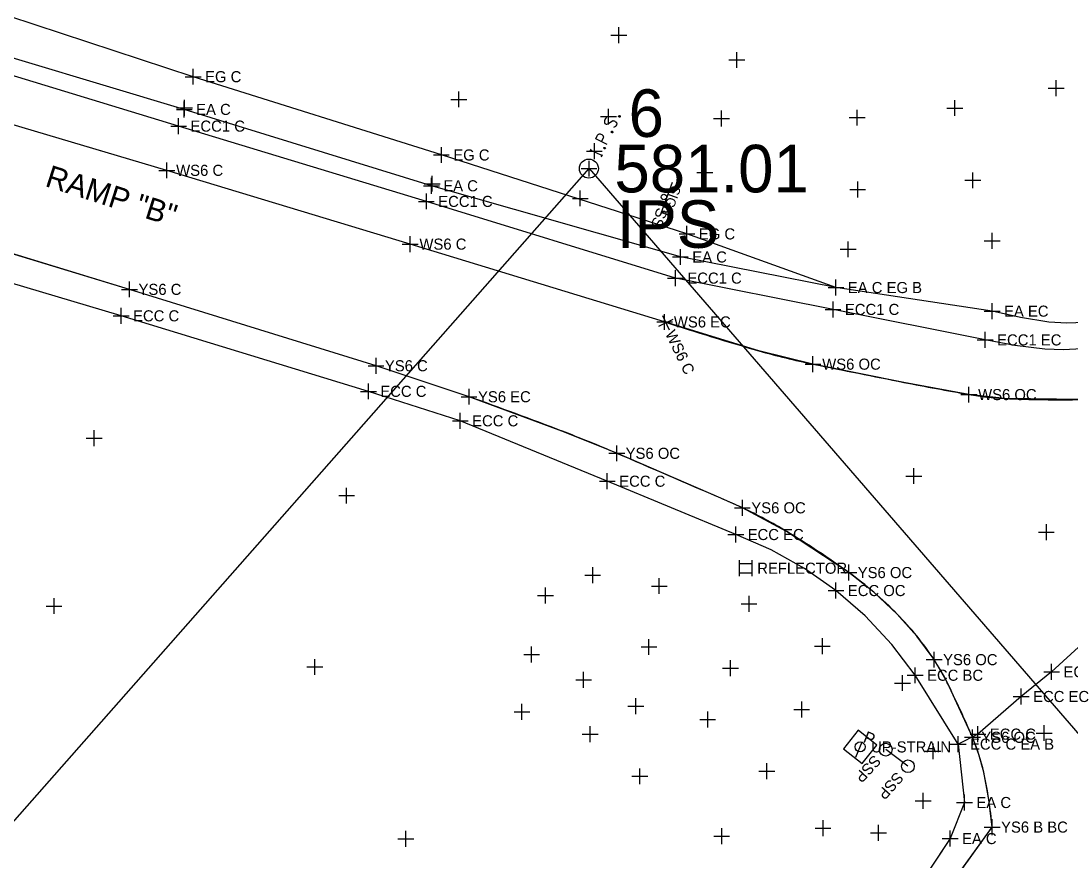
# Model space of a CAD drawing. Extents: x 1324236 to 1326110, y 459090 to 460782.
# Drawn here: x 1325183.3 to 1325315.8, y 460303.9 to 460409.8 of the extents above; entities that cross this region are included whole.
import ezdxf

# ---------------------------------------------------------------- set-up
doc = ezdxf.new("R2010")
doc.units = 0
for name, color, linetype in [('DR_X_Ditch', 7, 'Continuous'), ('DT_X_Contour_Major', 7, 'Continuous'), ('DT_X_Contour_Minor', 7, 'Continuous'), ('DT_X_Terrain_Ground_Line', 7, 'Continuous'), ('DT_X_Void', 7, 'Continuous'), ('DV_X_Property_Line', 7, 'Continuous'), ('E-RW-ODOT', 7, 'Continuous'), ('PM_X_Edge_Line', 7, 'Continuous'), ('PV_X_Shoulder', 7, 'Continuous'), ('PV_X_Shoulder_Aggregate', 7, 'Continuous'), ('RD_X_Concrete_Barrier', 7, 'Continuous'), ('RD_X_Text', 7, 'Continuous'), ('RW_X_CL', 7, 'Continuous'), ('RW_X_Esmt_SH', 7, 'Continuous'), ('SG_X_Foundation', 7, 'Continuous')]:
    doc.layers.add(name, color=color, linetype=linetype)

msp = doc.modelspace()

# ---------------------------------------------------------------- linework, layer by layer
at = {"layer": 'DR_X_Ditch'}
for p, q in [((1325301.57, 460318.51), (1325302.38, 460311.14)), ((1325302.38, 460311.14), (1325300.56, 460306.59)), ((1325300.56, 460306.59), (1325287.22, 460286.49))]:
    msp.add_line(p, q, dxfattribs=at)
for points in [[(1325317.23, 460361.99), (1325307.45, 460362.12), (1325307.45, 460362.12), (1325302.92, 460362.62), (1325302.92, 460362.62), (1325294.72, 460364.16), (1325294.72, 460364.16), (1325283.25, 460366.46), (1325283.25, 460366.46), (1325276.4, 460368.15), (1325276.4, 460368.15), (1325264.53, 460371.79), (1325264.53, 460371.79), (1325232.42, 460381.61), (1325201.72, 460390.92), (1325171.39, 460399.9)], [(1325305.86, 460308.04), (1325305.44, 460311.51), (1325304.8, 460314.95), (1325304.8, 460314.95), (1325304.19, 460317.19), (1325303.38, 460319.37), (1325303.38, 460319.37), (1325300.17, 460326.34), (1325300.17, 460326.34), (1325298.54, 460329.17), (1325298.54, 460329.17), (1325296.34, 460332.15), (1325293.87, 460334.92), (1325293.87, 460334.92), (1325290.94, 460337.67), (1325287.78, 460340.16), (1325287.78, 460340.16), (1325279.93, 460345.35), (1325279.93, 460345.35), (1325274.34, 460348.33), (1325274.34, 460348.33), (1325271.63, 460349.54), (1325271.63, 460349.54), (1325258.49, 460355.21), (1325258.49, 460355.21), (1325251.56, 460358.02), (1325251.56, 460358.02), (1325239.85, 460362.35), (1325239.85, 460362.35), (1325228.11, 460366.26), (1325197.01, 460375.9), (1325166.97, 460385.03)], [(1325301.57, 460318.51), (1325302.38, 460311.14), (1325300.56, 460306.59), (1325287.22, 460286.49), (1325268.79, 460261.45), (1325251.49, 460239.07), (1325233.13, 460213.12), (1325215.71, 460188.93), (1325205.67, 460177.31)], [(1325301.15, 460301.5), (1325305.86, 460308.04)]]:
    msp.add_lwpolyline(points, dxfattribs=at)
at = {"layer": 'DT_X_Contour_Major'}
for points in [[(1325257.22, 460397.56), (1325257.19, 460397.55), (1325257.15, 460397.53), (1325257.08, 460397.45), (1325257, 460397.35), (1325256.97, 460397.27), (1325256.95, 460397.24), (1325256.93, 460397.1), (1325256.94, 460396.96), (1325257, 460396.84), (1325257.08, 460396.78), (1325257.15, 460396.75), (1325257.25, 460396.73), (1325257.37, 460396.77), (1325257.97, 460397.16), (1325258.04, 460397.19), (1325258.09, 460397.18), (1325258.17, 460397.17), (1325258.24, 460397.14), (1325258.3, 460397.1), (1325258.34, 460397.07), (1325258.39, 460397.02), (1325258.43, 460396.98), (1325258.45, 460396.94), (1325258.47, 460396.9), (1325258.48, 460396.85), (1325258.49, 460396.8), (1325258.48, 460396.77), (1325258.45, 460396.67), (1325258.39, 460396.53), (1325258.32, 460396.46), (1325258.18, 460396.36), (1325258.07, 460396.32)], [(1325258.72, 460397.75), (1325258.75, 460397.8), (1325258.78, 460397.82), (1325258.84, 460397.83), (1325258.9, 460397.8), (1325258.93, 460397.75), (1325258.94, 460397.71), (1325258.92, 460397.66), (1325258.88, 460397.64), (1325258.82, 460397.63), (1325258.76, 460397.66), (1325258.73, 460397.71), (1325258.72, 460397.75)], [(1325257.29, 460394.2), (1325255.84, 460394.88), (1325256.07, 460395.36), (1325256.1, 460395.4), (1325256.16, 460395.46), (1325256.19, 460395.48), (1325256.23, 460395.5), (1325256.31, 460395.51), (1325256.38, 460395.52), (1325256.48, 460395.49), (1325256.61, 460395.43), (1325256.66, 460395.4), (1325256.71, 460395.35), (1325256.78, 460395.27), (1325256.79, 460395.21), (1325256.8, 460395.17), (1325256.8, 460395.11), (1325256.77, 460395.03), (1325256.55, 460394.55)], [(1325257.79, 460395.78), (1325257.82, 460395.83), (1325257.85, 460395.85), (1325257.91, 460395.85), (1325257.97, 460395.83), (1325258, 460395.78), (1325258.01, 460395.74), (1325257.99, 460395.69), (1325257.95, 460395.67), (1325257.89, 460395.66), (1325257.83, 460395.69), (1325257.8, 460395.74), (1325257.79, 460395.78)], [(1325255.1, 460393.3), (1325255.25, 460393.62)], [(1325256.62, 460392.78), (1325255.17, 460393.46)], [(1325256.84, 460393.74), (1325256.86, 460393.79), (1325256.9, 460393.81), (1325256.96, 460393.82), (1325257.01, 460393.79), (1325257.05, 460393.74), (1325257.05, 460393.7), (1325257.03, 460393.65), (1325256.99, 460393.63), (1325256.93, 460393.62), (1325256.88, 460393.65), (1325256.85, 460393.7), (1325256.84, 460393.74)], [(1325256.55, 460392.62), (1325256.7, 460392.94)]]:
    msp.add_lwpolyline(points, dxfattribs=at)
msp.add_circle((1325254.97, 460391.14), 1.2, dxfattribs=at)
at = {"layer": 'DT_X_Contour_Minor'}
for p, q in [((1325265.47, 460389.37), (1325264.07, 460385.49)), ((1325295.24, 460315.72), (1325292.43, 460317.81))]:
    msp.add_line(p, q, dxfattribs=at)
for centre, radius in [((1325264.44, 460387.55), 0.344), ((1325292.43, 460317.81), 0.8), ((1325295.24, 460315.72), 0.8)]:
    msp.add_circle(centre, radius, dxfattribs=at)
at = {"layer": 'DT_X_Terrain_Ground_Line'}
for p, q in [((1325273.92, 460341.71), (1325273.92, 460339.71)), ((1325275.52, 460341.71), (1325275.52, 460339.71)), ((1325273.92, 460341.31), (1325275.52, 460341.31)), ((1325273.92, 460340.11), (1325275.52, 460340.11))]:
    msp.add_line(p, q, dxfattribs=at)
at = {"layer": 'DV_X_Property_Line'}
for p, q in [((1325204.04, 460402.74), (1325206.04, 460402.74)), ((1325205.04, 460401.74), (1325205.04, 460403.74)), ((1325202.91, 460398.61), (1325204.91, 460398.61)), ((1325203.91, 460397.61), (1325203.91, 460399.61)), ((1325203.2, 460395.5), (1325203.2, 460397.5)), ((1325202.2, 460396.5), (1325204.2, 460396.5)), ((1325236.36, 460391.86), (1325236.36, 460393.86)), ((1325235.36, 460392.86), (1325237.36, 460392.86)), ((1325235.1, 460387.97), (1325235.1, 460389.97)), ((1325234.1, 460388.97), (1325236.1, 460388.97)), ((1325234.46, 460386), (1325234.46, 460388)), ((1325233.46, 460387), (1325235.46, 460387)), ((1325266.35, 460382.9), (1325268.35, 460382.9)), ((1325267.35, 460381.9), (1325267.35, 460383.9)), ((1325266.52, 460378.99), (1325266.52, 460380.99)), ((1325265.52, 460379.99), (1325267.52, 460379.99)), ((1325265.9, 460376.32), (1325265.9, 460378.32)), ((1325264.9, 460377.32), (1325266.9, 460377.32)), ((1325285.15, 460376.13), (1325287.15, 460376.13)), ((1325286.15, 460375.13), (1325286.15, 460377.13)), ((1325195.95, 460371.56), (1325195.95, 460373.56)), ((1325285.78, 460372.37), (1325285.78, 460374.37)), ((1325305.86, 460372.15), (1325305.86, 460374.15)), ((1325194.95, 460372.56), (1325196.95, 460372.56)), ((1325284.78, 460373.37), (1325286.78, 460373.37)), ((1325304.86, 460373.15), (1325306.86, 460373.15)), ((1325303.99, 460369.52), (1325305.99, 460369.52)), ((1325304.99, 460368.52), (1325304.99, 460370.52)), ((1325226.15, 460363.03), (1325228.15, 460363.03)), ((1325227.15, 460362.03), (1325227.15, 460364.03)), ((1325238.74, 460358.31), (1325238.74, 460360.31)), ((1325237.74, 460359.31), (1325239.74, 460359.31)), ((1325257.3, 460350.69), (1325257.3, 460352.69)), ((1325256.3, 460351.69), (1325258.3, 460351.69)), ((1325273.51, 460343.96), (1325273.51, 460345.96)), ((1325272.51, 460344.96), (1325274.51, 460344.96)), ((1325285.15, 460337.89), (1325287.15, 460337.89)), ((1325286.15, 460336.89), (1325286.15, 460338.89)), ((1325313.37, 460326.63), (1325313.37, 460328.63)), ((1325295.15, 460327.2), (1325297.15, 460327.2)), ((1325296.15, 460326.2), (1325296.15, 460328.2)), ((1325312.37, 460327.63), (1325314.37, 460327.63)), ((1325308.53, 460324.52), (1325310.53, 460324.52)), ((1325309.53, 460323.52), (1325309.53, 460325.52)), ((1325304.07, 460318.77), (1325304.07, 460320.77)), ((1325301.57, 460317.51), (1325301.57, 460319.51)), ((1325303.07, 460319.77), (1325305.07, 460319.77)), ((1325300.57, 460318.51), (1325302.57, 460318.51)), ((1325302.38, 460310.14), (1325302.38, 460312.14)), ((1325301.38, 460311.14), (1325303.38, 460311.14)), ((1325300.56, 460305.59), (1325300.56, 460307.59)), ((1325299.56, 460306.59), (1325301.56, 460306.59))]:
    msp.add_line(p, q, dxfattribs=at)
at = {"layer": 'E-RW-ODOT'}
for p, q in [((1325254.99, 460390.14), (1325254.99, 460392.14)), ((1325084.27, 460197.5), (1325254.99, 460391.14)), ((1325253.99, 460391.14), (1325255.99, 460391.14)), ((1325254.99, 460391.14), (1325401.65, 460221.67))]:
    msp.add_line(p, q, dxfattribs=at)
at = {"layer": 'PM_X_Edge_Line'}
for p, q in [((1325201.72, 460390.92), (1325171.39, 460399.9)), ((1325232.42, 460381.61), (1325201.72, 460390.92)), ((1325197.01, 460375.9), (1325166.97, 460385.03)), ((1325264.53, 460371.79), (1325232.42, 460381.61)), ((1325228.11, 460366.26), (1325197.01, 460375.9)), ((1325239.85, 460362.35), (1325228.11, 460366.26)), ((1325201.59, 460163.28), (1325305.86, 460308.04))]:
    msp.add_line(p, q, dxfattribs=at)
msp.add_lwpolyline([(1325201.59, 460163.28), (1325254.57, 460236.83), (1325305.86, 460308.04)], dxfattribs=at)
for centre, radius, start, end in [((1325358.09, 460655.03), 298.28, 251.7213, 254.1071), ((1325302.73, 460460.6), 96.13, 254.1071, 258.3103), ((1325495.55, 461392.55), 1047.81, 258.31033, 258.95006), ((1325396.93, 460887.55), 533.27, 258.9501, 259.8468), ((1325060.34, 459858.97), 534.43, 69.0355, 70.3735), ((1325308.98, 460396.41), 34.32, 259.8468, 267.4556), ((1325314.47, 460520.12), 158.15, 267.4556, 270.9983), ((1325182.91, 460178.86), 191.87, 66.8023, 69.0355), ((1324033.98, 457497.91), 3108.62, 66.53849, 66.80233), ((1325218.3, 460226.67), 133.95, 65.2674, 66.5385), ((1325251.23, 460298.15), 55.24, 58.6975, 65.2674), ((1325216.48, 460241.01), 122.13, 54.2801, 58.6975), ((1325260.56, 460302.3), 46.63, 44.3975, 54.2801), ((1325265.53, 460307.17), 39.67, 33.6815, 44.3975), ((1325277.5, 460315.15), 25.28, 26.2869, 33.6815), ((1325174.66, 460264.35), 139.98, 23.146, 26.2869), ((1325280.64, 460309.65), 24.73, 12.3586, 23.146), ((1325250.27, 460303), 55.82, 5.1844, 12.3586)]:
    msp.add_arc(centre, radius, start, end, dxfattribs=at)
at = {"layer": 'PV_X_Shoulder'}
for points in [[(1325350.45, 460385.12), (1325345.12, 460380.73), (1325343.34, 460379.33), (1325341.02, 460377.79), (1325338.54, 460376.54), (1325334.16, 460374.85), (1325329.68, 460373.48), (1325325.72, 460372.67), (1325317.54, 460371.7), (1325315.28, 460371.62), (1325313.02, 460371.78), (1325309.42, 460372.34), (1325305.86, 460373.15), (1325286.15, 460376.13), (1325266.52, 460379.99), (1325235.1, 460388.97), (1325203.91, 460398.61), (1325173.61, 460407.67)], [(1325317.16, 460368.39), (1325314.85, 460368.25), (1325312.53, 460368.35), (1325312.53, 460368.35), (1325308.74, 460368.82), (1325304.99, 460369.52), (1325304.99, 460369.52), (1325285.78, 460373.37), (1325265.9, 460377.32), (1325234.46, 460387), (1325203.2, 460396.5), (1325172.92, 460405.69)], [(1325318.25, 460332.11), (1325313.37, 460327.63), (1325313.37, 460327.63), (1325309.53, 460324.52), (1325309.53, 460324.52), (1325304.07, 460319.77), (1325301.57, 460318.51), (1325296.15, 460327.2), (1325293.19, 460331.1), (1325289.84, 460334.68), (1325286.15, 460337.89), (1325286.15, 460337.89), (1325282.19, 460340.67), (1325277.96, 460343.04), (1325273.51, 460344.96), (1325273.51, 460344.96), (1325257.3, 460351.69), (1325238.74, 460359.31), (1325227.15, 460363.03), (1325195.95, 460372.56), (1325165.83, 460381.51)]]:
    msp.add_lwpolyline(points, dxfattribs=at)
at = {"layer": 'PV_X_Shoulder_Aggregate'}
msp.add_lwpolyline([(1325286.15, 460376.13), (1325267.35, 460382.9), (1325236.36, 460392.86), (1325205.04, 460402.74), (1325175.07, 460412.61), (1325145.55, 460421.9), (1325113.81, 460432.03), (1325082.13, 460441.54), (1325051.05, 460449.76), (1325019.35, 460459.28), (1324987.54, 460468.89), (1324956.75, 460477.62), (1324924.35, 460486.71), (1324893.18, 460495.82), (1324861.31, 460505.68), (1324828.49, 460513.21)], dxfattribs=at)
at = {"layer": 'RD_X_Concrete_Barrier'}
msp.add_line((1325288.67, 460316.87), (1325289.47, 460318.81), dxfattribs=at)
msp.add_circle((1325289.2, 460318.16), 0.63, dxfattribs=at)
at = {"layer": 'RW_X_CL'}
for p, q in [((1325257.75, 460407.97), (1325259.75, 460407.97)), ((1325258.75, 460406.97), (1325258.75, 460408.97)), ((1325273.65, 460403.85), (1325273.65, 460405.85)), ((1325272.65, 460404.85), (1325274.65, 460404.85)), ((1325312.93, 460401.29), (1325314.93, 460401.29)), ((1325313.93, 460400.29), (1325313.93, 460402.29)), ((1325238.55, 460398.88), (1325238.55, 460400.88)), ((1325202.94, 460398.8), (1325204.94, 460398.8)), ((1325203.94, 460397.8), (1325203.94, 460399.8)), ((1325237.55, 460399.88), (1325239.55, 460399.88)), ((1325257.44, 460396.7), (1325257.44, 460398.7)), ((1325300.15, 460398.78), (1325302.15, 460398.78)), ((1325301.15, 460397.78), (1325301.15, 460399.78)), ((1325256.44, 460397.7), (1325258.44, 460397.7)), ((1325270.71, 460397.47), (1325272.71, 460397.47)), ((1325271.71, 460396.47), (1325271.71, 460398.47)), ((1325287.83, 460397.57), (1325289.83, 460397.57)), ((1325288.83, 460396.57), (1325288.83, 460398.57)), ((1325254.66, 460393.35), (1325256.66, 460393.35)), ((1325255.66, 460392.35), (1325255.66, 460394.35)), ((1325200.72, 460390.92), (1325202.72, 460390.92)), ((1325201.72, 460389.92), (1325201.72, 460391.92)), ((1325268.61, 460390.65), (1325270.61, 460390.65)), ((1325269.61, 460389.65), (1325269.61, 460391.65)), ((1325303.42, 460388.66), (1325303.42, 460390.66)), ((1325235.19, 460388.23), (1325235.19, 460390.23)), ((1325288.9, 460387.5), (1325288.9, 460389.5)), ((1325302.42, 460389.66), (1325304.42, 460389.66)), ((1325234.19, 460389.23), (1325236.19, 460389.23)), ((1325253.89, 460386.38), (1325253.89, 460388.38)), ((1325287.9, 460388.5), (1325289.9, 460388.5)), ((1325252.89, 460387.38), (1325254.89, 460387.38)), ((1325305.86, 460381.03), (1325305.86, 460383.03)), ((1325231.42, 460381.61), (1325233.42, 460381.61)), ((1325232.42, 460380.61), (1325232.42, 460382.61)), ((1325287.7, 460379.96), (1325287.7, 460381.96)), ((1325304.86, 460382.03), (1325306.86, 460382.03)), ((1325286.7, 460380.96), (1325288.7, 460380.96)), ((1325197.01, 460374.9), (1325197.01, 460376.9)), ((1325196.01, 460375.9), (1325198.01, 460375.9)), ((1325263.78, 460371.26), (1325265.59, 460372.12)), ((1325264.25, 460372.59), (1325265.12, 460370.79)), ((1325264.53, 460370.79), (1325264.53, 460372.79)), ((1325263.53, 460371.79), (1325265.53, 460371.79)), ((1325228.11, 460365.26), (1325228.11, 460367.26)), ((1325283.25, 460365.46), (1325283.25, 460367.46)), ((1325227.11, 460366.26), (1325229.11, 460366.26)), ((1325282.25, 460366.46), (1325284.25, 460366.46)), ((1325239.85, 460361.35), (1325239.85, 460363.35)), ((1325302.92, 460361.62), (1325302.92, 460363.62)), ((1325238.85, 460362.35), (1325240.85, 460362.35)), ((1325301.92, 460362.62), (1325303.92, 460362.62)), ((1325192.54, 460356.11), (1325192.54, 460358.11)), ((1325191.54, 460357.11), (1325193.54, 460357.11)), ((1325258.49, 460354.21), (1325258.49, 460356.21)), ((1325257.49, 460355.21), (1325259.49, 460355.21)), ((1325294.99, 460352.34), (1325296.99, 460352.34)), ((1325295.99, 460351.34), (1325295.99, 460353.34)), ((1325223.4, 460349.87), (1325225.4, 460349.87)), ((1325224.4, 460348.87), (1325224.4, 460350.87)), ((1325273.34, 460348.33), (1325275.34, 460348.33)), ((1325274.34, 460347.33), (1325274.34, 460349.33)), ((1325312.7, 460344.26), (1325312.7, 460346.26)), ((1325311.7, 460345.26), (1325313.7, 460345.26)), ((1325255.45, 460338.84), (1325255.45, 460340.84)), ((1325287.78, 460339.16), (1325287.78, 460341.16)), ((1325254.45, 460339.84), (1325256.45, 460339.84)), ((1325263.86, 460337.46), (1325263.86, 460339.46)), ((1325286.78, 460340.16), (1325288.78, 460340.16)), ((1325249.49, 460336.27), (1325249.49, 460338.27)), ((1325262.86, 460338.46), (1325264.86, 460338.46)), ((1325187.48, 460334.94), (1325187.48, 460336.94)), ((1325248.49, 460337.27), (1325250.49, 460337.27)), ((1325275.18, 460335.22), (1325275.18, 460337.22)), ((1325186.48, 460335.94), (1325188.48, 460335.94)), ((1325274.18, 460336.22), (1325276.18, 460336.22)), ((1325262.55, 460329.77), (1325262.55, 460331.77)), ((1325284.44, 460329.88), (1325284.44, 460331.88)), ((1325246.75, 460329.82), (1325248.75, 460329.82)), ((1325247.75, 460328.82), (1325247.75, 460330.82)), ((1325261.55, 460330.77), (1325263.55, 460330.77)), ((1325283.44, 460330.88), (1325285.44, 460330.88)), ((1325298.54, 460328.17), (1325298.54, 460330.17)), ((1325220.39, 460327.25), (1325220.39, 460329.25)), ((1325272.84, 460327.1), (1325272.84, 460329.1)), ((1325297.54, 460329.17), (1325299.54, 460329.17)), ((1325219.39, 460328.25), (1325221.39, 460328.25)), ((1325254.31, 460325.63), (1325254.31, 460327.63)), ((1325271.84, 460328.1), (1325273.84, 460328.1)), ((1325294.55, 460325.22), (1325294.55, 460327.22)), ((1325253.31, 460326.63), (1325255.31, 460326.63)), ((1325293.55, 460326.22), (1325295.55, 460326.22)), ((1325246.53, 460321.59), (1325246.53, 460323.59)), ((1325259.89, 460323.29), (1325261.89, 460323.29)), ((1325260.89, 460322.29), (1325260.89, 460324.29)), ((1325281.83, 460321.88), (1325281.83, 460323.88)), ((1325245.53, 460322.59), (1325247.53, 460322.59)), ((1325269.97, 460320.61), (1325269.97, 460322.61)), ((1325280.83, 460322.88), (1325282.83, 460322.88)), ((1325255.13, 460318.76), (1325255.13, 460320.76)), ((1325268.97, 460321.61), (1325270.97, 460321.61)), ((1325312.42, 460318.91), (1325312.42, 460320.91)), ((1325254.13, 460319.76), (1325256.13, 460319.76)), ((1325302.38, 460319.37), (1325304.38, 460319.37)), ((1325303.38, 460318.37), (1325303.38, 460320.37)), ((1325311.42, 460319.91), (1325313.42, 460319.91)), ((1325298.4, 460316.6), (1325298.4, 460318.6)), ((1325297.4, 460317.6), (1325299.4, 460317.6)), ((1325261.41, 460313.45), (1325261.41, 460315.45)), ((1325277.43, 460314.09), (1325277.43, 460316.09)), ((1325260.41, 460314.45), (1325262.41, 460314.45)), ((1325276.43, 460315.09), (1325278.43, 460315.09)), ((1325296.16, 460311.36), (1325298.16, 460311.36)), ((1325297.16, 460310.36), (1325297.16, 460312.36)), ((1325284.52, 460306.91), (1325284.52, 460308.91)), ((1325305.86, 460307.04), (1325305.86, 460309.04)), ((1325231.87, 460305.56), (1325231.87, 460307.56)), ((1325271.73, 460305.89), (1325271.73, 460307.89)), ((1325283.52, 460307.91), (1325285.52, 460307.91)), ((1325290.51, 460307.32), (1325292.51, 460307.32)), ((1325291.51, 460306.32), (1325291.51, 460308.32)), ((1325304.86, 460308.04), (1325306.86, 460308.04)), ((1325230.87, 460306.56), (1325232.87, 460306.56)), ((1325270.73, 460306.89), (1325272.73, 460306.89))]:
    msp.add_line(p, q, dxfattribs=at)
at = {"layer": 'SG_X_Foundation'}
for p, q in [((1325288.97, 460320.27), (1325287.09, 460317.93)), ((1325291.31, 460318.39), (1325288.97, 460320.27)), ((1325287.09, 460317.93), (1325289.44, 460316.05)), ((1325289.44, 460316.05), (1325291.31, 460318.39))]:
    msp.add_line(p, q, dxfattribs=at)
msp.add_lwpolyline([(1325287.09, 460317.93), (1325289.44, 460316.05), (1325291.31, 460318.39), (1325288.97, 460320.27)], close=True, dxfattribs=at)

# ---------------------------------------------------------------- texts
at = {"layer": 'DT_X_Contour_Minor'}
for s, height, rotation, p in [('SIGN', 1.205, 250.1512, (1325265.48, 460389.08)), ('SS', 1.4, 250.1512, (1325263.62, 460386.31)), ('SSP', 1.4, 227.3158, (1325290.93, 460317.23)), ('SSP', 1.4, 228.4432, (1325293.76, 460315.11))]:
    msp.add_text(s, height=height, rotation=rotation, dxfattribs=at).set_placement(p)
at = {"layer": 'DT_X_Void'}
msp.add_text('UP-STRAIN', height=1.4, dxfattribs=at).set_placement((1325290.59, 460317.46))
at = {"layer": 'DV_X_Property_Line'}
for s, p in [('EG C', (1325206.54, 460402.04)), ('EA C', (1325205.41, 460397.91)), ('ECC1 C', (1325204.7, 460395.8)), ('EG C', (1325237.86, 460392.16)), ('EA C', (1325236.6, 460388.27)), ('ECC1 C', (1325235.96, 460386.3)), ('EG C', (1325268.85, 460382.2)), ('EA C', (1325268.02, 460379.29)), ('ECC1 C', (1325267.4, 460376.62)), ('EA C EG B', (1325287.65, 460375.43)), ('ECC1 C', (1325287.28, 460372.67)), ('EA EC', (1325307.36, 460372.45)), ('ECC C', (1325197.45, 460371.86)), ('ECC1 EC', (1325306.49, 460368.82)), ('ECC C', (1325228.65, 460362.33)), ('ECC C', (1325240.24, 460358.61)), ('ECC C', (1325258.8, 460350.99)), ('ECC EC', (1325275.01, 460344.26)), ('ECC OC', (1325287.65, 460337.19)), ('ECC BC', (1325297.65, 460326.5)), ('ECC OC', (1325314.87, 460326.93)), ('ECC EC', (1325311.03, 460323.82)), ('ECC C', (1325305.57, 460319.07)), ('ECC C EA B', (1325303.07, 460317.81)), ('EA C', (1325303.88, 460310.44)), ('EA C', (1325302.06, 460305.89))]:
    msp.add_text(s, height=1.4, dxfattribs=at).set_placement(p)
at = {"layer": 'E-RW-ODOT'}
for s, p in [('6', (1325259.98, 460395.14)), ('581.01', (1325258.19, 460388.14)), ('IPS', (1325258.49, 460381.14))]:
    msp.add_text(s, height=6, dxfattribs=at).set_placement(p)
at = {"layer": 'RD_X_Concrete_Barrier'}
msp.add_text('P', height=1.5, rotation=337.5827, dxfattribs=at).set_placement((1325289.47, 460318.81))
at = {"layer": 'RD_X_Text'}
msp.add_text('RAMP "B"', height=2.8, rotation=342.2913, dxfattribs=at).set_placement((1325186.22, 460388.96))
at = {"layer": 'RW_X_CL'}
for s, p in [('WS6 C', (1325202.89, 460390.22)), ('WS6 C', (1325233.59, 460380.91)), ('YS6 C', (1325198.14, 460375.2)), ('WS6 EC', (1325265.7, 460371.09)), ('YS6 C', (1325229.23, 460365.56)), ('WS6 OC', (1325284.42, 460365.76)), ('YS6 EC', (1325240.98, 460361.65)), ('WS6 OC', (1325304.09, 460361.92)), ('YS6 OC', (1325259.61, 460354.51)), ('YS6 OC', (1325275.47, 460347.63)), ('YS6 OC', (1325288.9, 460339.46)), ('YS6 OC', (1325299.67, 460328.47)), ('YS6 OC', (1325304.5, 460318.67)), ('YS6 B BC', (1325306.99, 460307.34))]:
    msp.add_text(s, height=1.4, dxfattribs=at).set_placement(p)
msp.add_text('WS6 C', height=1.4, rotation=295.6425, dxfattribs=at).set_placement((1325264.56, 460370.33))
at = {"layer": 'RW_X_Esmt_SH'}
msp.add_text('REFLECTOR', height=1.4, dxfattribs=at).set_placement((1325276.22, 460340.01))

doc.saveas('drawing.dxf')
